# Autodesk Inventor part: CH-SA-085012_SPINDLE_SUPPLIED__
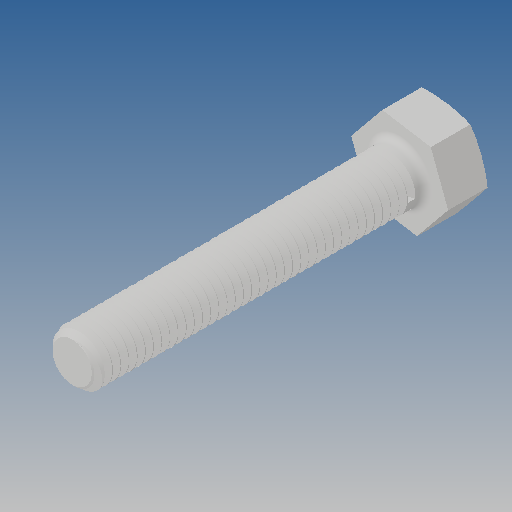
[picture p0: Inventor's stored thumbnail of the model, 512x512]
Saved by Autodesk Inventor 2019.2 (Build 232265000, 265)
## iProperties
Created: 2012-06
Part Number: CH-SA-085012_SPINDLE_SUPPLIED__
Material: Ogólny
Document SubType Name: Modeling
Designer: CADENGINEERING4
Density: 1 g/cm^3
Appearance: Domyślna
Author: CADENGINEERING4
Revision Number: 1LAST_VERSION
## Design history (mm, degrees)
feature "Baza1"
node "Bryła1"
